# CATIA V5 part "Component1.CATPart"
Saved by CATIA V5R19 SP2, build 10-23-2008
Part number: Component1
Definition: Component1
Nomenclature: Component1
Source: Unknown
Bounding box of the stored display mesh (mm): x -4.283 to 0.4, y 0 to 2.367, z 0 to 3.3
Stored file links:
  Z:\fausse table rondelle-20220905T211342Z-001\fausse table rondelle\Component1.CATPart
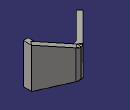
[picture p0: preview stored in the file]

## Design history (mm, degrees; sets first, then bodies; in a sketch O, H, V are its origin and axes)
AxisSystem1: origin (0, 0, 0), X (1, 0, 0), Y (0, 1, 0), Z (0, 0, 1)
Body1 "Body1" (main body)
  Solid1: solid without history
